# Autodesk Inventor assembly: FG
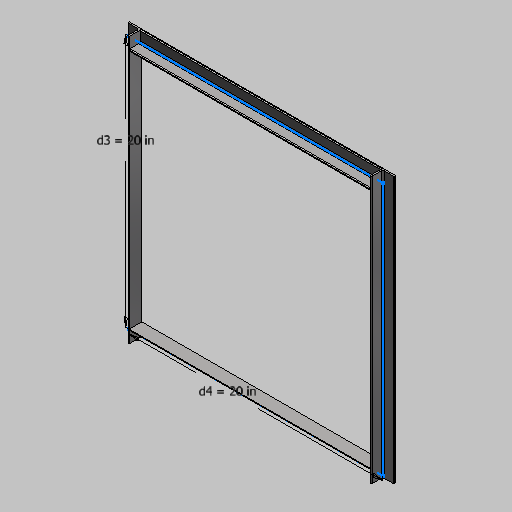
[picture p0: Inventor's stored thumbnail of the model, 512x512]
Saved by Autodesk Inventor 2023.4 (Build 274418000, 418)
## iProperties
Created: 2023-10
Part Number: FG
Material: Steel, Mild
Document SubType Name: Assembly
Designer: Fred L.
Mass: 2431.55 g
Surface Area: 2020.83 cm^2
Volume: 309.752 cm^3
Density: 7.85 g/cm^3
_SolveAssemblyDoc: Frame Generator Solve Assembly
_Version: 25.0.0
Quantity: 0
Mass: 5.36
Author: Fred L.
Revision Number: 00
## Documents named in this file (3)
- C:\Vault Workspace\Designs\_Fred\IV Forum\FG2\FG.iam
- C:\Vault Workspace\Designs\_Fred\IV Forum\FG2\FG-Master.ipt
- C:\Vault Workspace\Designs\_Fred\IV Forum\FG2\FG\Frame\Frame 1698438166051.iam
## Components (2 placed, 2 different names)
1. FG-Master:1
2. Frame 1698438166051:1 [sub-assembly]
